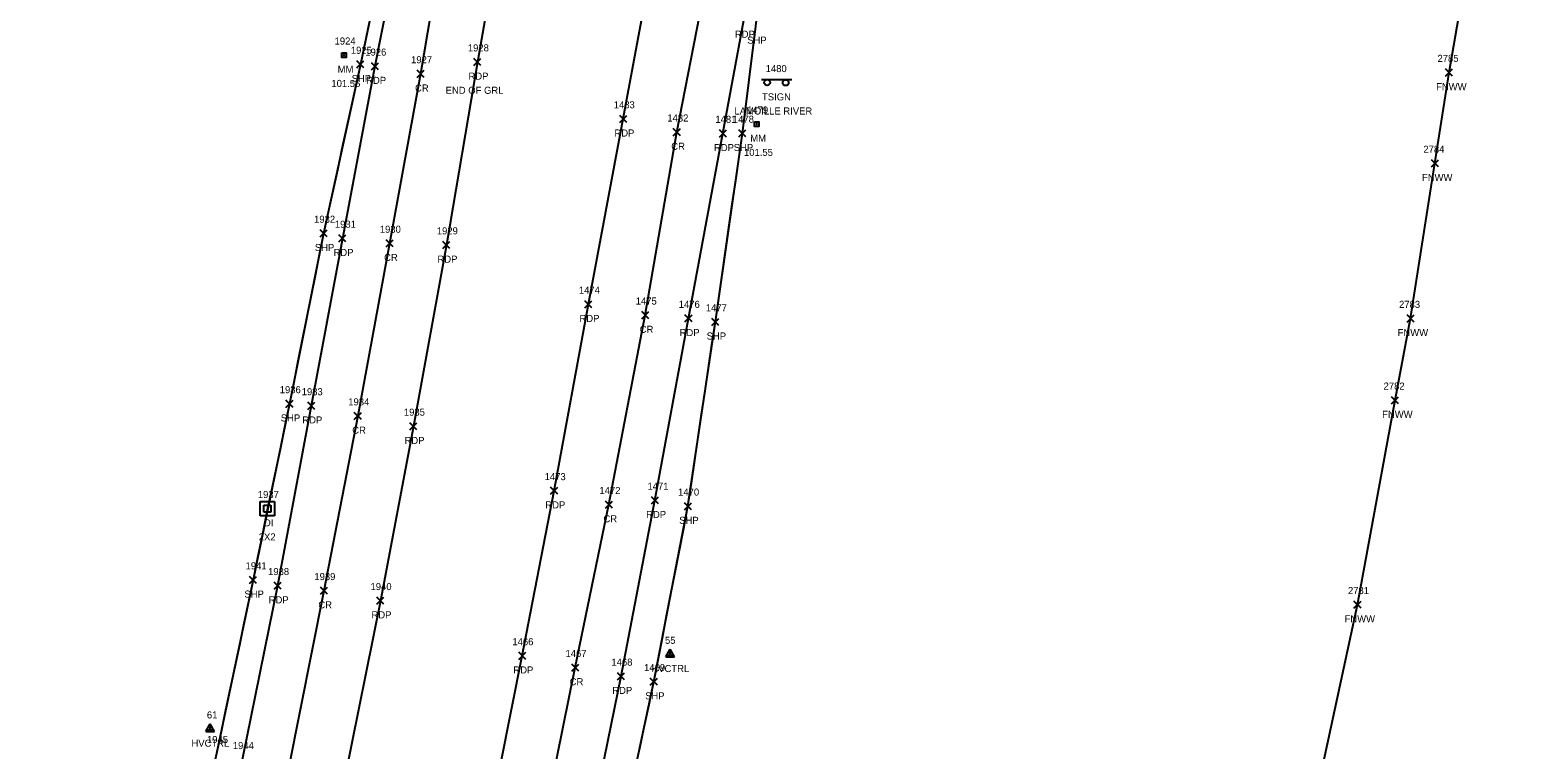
# Model space of a CAD drawing. Extents: x 1472022 to 1479249, y 777216 to 786527.
# Drawn here: x 1473450.2 to 1473876.7, y 779074.7 to 779278.4 of the extents above; entities that cross this region are included whole.
import ezdxf

# ---------------------------------------------------------------- set-up
doc = ezdxf.new("R2010")
doc.units = 0
for name, color, linetype in [('C_A', 7, 'Continuous'), ('C_I', 7, 'Continuous'), ('CPSM', 7, 'Continuous'), ('D_A', 7, 'Continuous'), ('D_C', 7, 'Continuous'), ('D_I', 7, 'Continuous'), ('DS', 7, 'Continuous'), ('L_A', 7, 'Continuous'), ('L_I', 7, 'Continuous'), ('L_TIC', 7, 'Continuous'), ('LFNC', 7, 'Continuous'), ('LSOGP', 7, 'Continuous'), ('P_A', 7, 'Continuous'), ('P_C', 7, 'Continuous'), ('P_I', 7, 'Continuous'), ('P_TIC', 7, 'Continuous'), ('PET', 7, 'Continuous'), ('PRC', 7, 'Continuous'), ('PSP', 7, 'Continuous'), ('S_A', 7, 'Continuous'), ('S_C', 7, 'Continuous'), ('S_I', 7, 'Continuous'), ('SRM', 7, 'Continuous'), ('SSGN', 7, 'Continuous')]:
    doc.layers.add(name, color=color, linetype=linetype)

msp = doc.modelspace()

# ---------------------------------------------------------------- linework, layer by layer
at = {"layer": 'CPSM'}
for p, q in [((1473630.02, 779100.99), (1473631.27, 779103.15)), ((1473630.02, 779100.99), (1473631.27, 779101.71)), ((1473630.02, 779100.99), (1473632.52, 779100.99)), ((1473632.52, 779100.99), (1473631.27, 779103.15)), ((1473631.27, 779101.71), (1473631.27, 779103.15)), ((1473631.27, 779101.71), (1473631.27, 779101.71)), ((1473631.27, 779101.71), (1473632.52, 779100.99)), ((1473499.93, 779079.86), (1473501.18, 779082.03)), ((1473499.93, 779079.86), (1473501.18, 779080.58)), ((1473499.93, 779079.86), (1473502.43, 779079.86)), ((1473502.43, 779079.86), (1473501.18, 779082.03)), ((1473501.18, 779080.58), (1473501.18, 779082.03)), ((1473501.18, 779080.58), (1473501.18, 779080.58)), ((1473501.18, 779080.58), (1473502.43, 779079.86))]:
    msp.add_line(p, q, dxfattribs=at)
at = {"layer": 'DS'}
for p, q in [((1473515.32, 779144.97), (1473519.32, 779144.97)), ((1473515.32, 779140.97), (1473515.32, 779144.97)), ((1473516.32, 779141.97), (1473516.32, 779143.97)), ((1473516.32, 779143.97), (1473518.32, 779143.97)), ((1473517.33, 779142.97), (1473517.33, 779142.97)), ((1473517.33, 779142.97), (1473517.33, 779142.97)), ((1473518.32, 779143.97), (1473518.32, 779141.97)), ((1473519.32, 779144.97), (1473519.32, 779140.97)), ((1473519.32, 779140.97), (1473515.32, 779140.97)), ((1473518.32, 779141.97), (1473516.32, 779141.97))]:
    msp.add_line(p, q, dxfattribs=at)
at = {"layer": 'L_TIC'}
for points in [[(1473850.55, 779265.41), (1473852.55, 779267.41)], [(1473852.55, 779265.41), (1473850.55, 779267.41)], [(1473846.56, 779239.7), (1473848.56, 779241.7)], [(1473848.56, 779239.7), (1473846.56, 779241.7)], [(1473839.68, 779195.79), (1473841.68, 779197.79)], [(1473841.68, 779195.79), (1473839.68, 779197.79)], [(1473835.3, 779172.66), (1473837.3, 779174.66)], [(1473837.3, 779172.66), (1473835.3, 779174.66)], [(1473824.67, 779114.79), (1473826.67, 779116.79)], [(1473826.67, 779114.79), (1473824.67, 779116.79)]]:
    msp.add_lwpolyline(points, dxfattribs=at)
at = {"layer": 'LFNC'}
msp.add_lwpolyline([(1473815.37, 779068.14), (1473825.67, 779115.79), (1473836.3, 779173.66), (1473840.68, 779196.79), (1473847.56, 779240.7), (1473851.55, 779266.41), (1473860.03, 779315.65), (1473865.47, 779349.75), (1473876.67, 779405.17)], dxfattribs=at)
at = {"layer": 'LSOGP'}
for points in [[(1473546.65, 779283.15), (1473545.15, 779275.93), (1473543.65, 779268.7), (1473542.35, 779262.72), (1473541.05, 779256.74), (1473539.74, 779250.77), (1473538.44, 779244.79), (1473537.14, 779238.81), (1473535.84, 779232.83), (1473534.54, 779226.85), (1473533.24, 779220.88), (1473532.03, 779214.85), (1473530.83, 779208.82), (1473529.62, 779202.79), (1473528.41, 779196.76), (1473527.21, 779190.73), (1473526, 779184.7), (1473524.8, 779178.67), (1473523.59, 779172.64), (1473522.3, 779166.41), (1473521.02, 779160.18), (1473519.73, 779153.95), (1473518.45, 779147.71), (1473517.33, 779142.97), (1473515.87, 779135.25), (1473514.59, 779129.02), (1473513.3, 779122.79), (1473512.01, 779116.64), (1473510.71, 779110.49), (1473509.42, 779104.35), (1473508.13, 779098.2), (1473506.83, 779092.05), (1473505.54, 779085.91), (1473504.24, 779079.76), (1473502.95, 779073.62)], [(1473622.56, 779074.68), (1473623.92, 779081.11), (1473625.28, 779087.55), (1473626.64, 779093.98), (1473627.85, 779100.19), (1473629.05, 779106.4), (1473630.26, 779112.61), (1473631.47, 779118.82), (1473632.67, 779125.03), (1473633.88, 779131.24), (1473635.09, 779137.45), (1473636.29, 779143.66), (1473637.26, 779150.18), (1473638.23, 779156.7), (1473639.2, 779163.22), (1473640.17, 779169.75), (1473641.15, 779176.27), (1473642.12, 779182.79), (1473643.09, 779189.31), (1473644.06, 779195.83), (1473645.01, 779202.5), (1473645.97, 779209.17), (1473646.92, 779215.84), (1473647.88, 779222.51), (1473648.84, 779229.18), (1473649.79, 779235.85), (1473650.75, 779242.51), (1473651.7, 779249.18), (1473652.66, 779256.78), (1473653.61, 779264.37), (1473654.56, 779271.97), (1473655.52, 779279.56)]]:
    msp.add_lwpolyline(points, dxfattribs=at)
at = {"layer": 'P_TIC'}
for points in [[(1473575.73, 779268.38), (1473577.73, 779270.38)], [(1473577.73, 779268.38), (1473575.73, 779270.38)], [(1473542.65, 779267.7), (1473544.65, 779269.7)], [(1473544.65, 779267.7), (1473542.65, 779269.7)], [(1473546.78, 779267.19), (1473548.78, 779269.19)], [(1473548.78, 779267.19), (1473546.78, 779269.19)], [(1473559.67, 779265.03), (1473561.67, 779267.03)], [(1473561.67, 779265.03), (1473559.67, 779267.03)], [(1473617, 779252.28), (1473619, 779254.28)], [(1473619, 779252.28), (1473617, 779254.28)], [(1473632.15, 779248.53), (1473634.15, 779250.53)], [(1473634.15, 779248.53), (1473632.15, 779250.53)], [(1473645.17, 779248.15), (1473647.17, 779250.15)], [(1473647.17, 779248.15), (1473645.17, 779250.15)], [(1473650.7, 779248.18), (1473652.7, 779250.18)], [(1473652.7, 779248.18), (1473650.7, 779250.18)], [(1473532.24, 779219.88), (1473534.24, 779221.88)], [(1473534.24, 779219.88), (1473532.24, 779221.88)], [(1473537.56, 779218.47), (1473539.56, 779220.47)], [(1473539.56, 779218.47), (1473537.56, 779220.47)], [(1473550.92, 779217.05), (1473552.92, 779219.05)], [(1473552.92, 779217.05), (1473550.92, 779219.05)], [(1473566.96, 779216.59), (1473568.96, 779218.59)], [(1473568.96, 779216.59), (1473566.96, 779218.59)], [(1473607.13, 779199.81), (1473609.13, 779201.81)], [(1473609.13, 779199.81), (1473607.13, 779201.81)], [(1473623.22, 779196.73), (1473625.22, 779198.73)], [(1473625.22, 779196.73), (1473623.22, 779198.73)], [(1473635.44, 779195.8), (1473637.44, 779197.8)], [(1473637.44, 779195.8), (1473635.44, 779197.8)], [(1473643.06, 779194.83), (1473645.06, 779196.83)], [(1473645.06, 779194.83), (1473643.06, 779196.83)], [(1473522.59, 779171.64), (1473524.59, 779173.64)], [(1473524.59, 779171.64), (1473522.59, 779173.64)], [(1473528.75, 779171.07), (1473530.75, 779173.07)], [(1473530.75, 779171.07), (1473528.75, 779173.07)], [(1473541.92, 779168.19), (1473543.92, 779170.19)], [(1473543.92, 779168.19), (1473541.92, 779170.19)], [(1473557.64, 779165.28), (1473559.64, 779167.28)], [(1473559.64, 779165.28), (1473557.64, 779167.28)], [(1473597.46, 779147.03), (1473599.46, 779149.03)], [(1473599.46, 779147.03), (1473597.46, 779149.03)], [(1473612.95, 779143.11), (1473614.95, 779145.11)], [(1473614.95, 779143.11), (1473612.95, 779145.11)], [(1473625.97, 779144.31), (1473627.97, 779146.31)], [(1473627.97, 779144.31), (1473625.97, 779146.31)], [(1473635.29, 779142.66), (1473637.29, 779144.66)], [(1473637.29, 779142.66), (1473635.29, 779144.66)], [(1473512.3, 779121.79), (1473514.3, 779123.79)], [(1473514.3, 779121.79), (1473512.3, 779123.79)], [(1473519.23, 779120.16), (1473521.23, 779122.16)], [(1473521.23, 779120.16), (1473519.23, 779122.16)], [(1473532.33, 779118.74), (1473534.33, 779120.74)], [(1473534.33, 779118.74), (1473532.33, 779120.74)], [(1473548.3, 779115.91), (1473550.3, 779117.91)], [(1473550.3, 779115.91), (1473548.3, 779117.91)], [(1473588.43, 779100.31), (1473590.43, 779102.31)], [(1473590.43, 779100.31), (1473588.43, 779102.31)], [(1473603.41, 779096.99), (1473605.41, 779098.99)], [(1473605.41, 779096.99), (1473603.41, 779098.99)], [(1473616.39, 779094.53), (1473618.39, 779096.53)], [(1473618.39, 779094.53), (1473616.39, 779096.53)], [(1473625.64, 779092.98), (1473627.64, 779094.98)], [(1473627.64, 779092.98), (1473625.64, 779094.98)]]:
    msp.add_lwpolyline(points, dxfattribs=at)
at = {"layer": 'PET'}
for points in [[(1473559.55, 779345.54), (1473562.13, 779344.85), (1473559.08, 779325.48), (1473547.78, 779268.19), (1473538.56, 779219.47), (1473529.75, 779172.07), (1473520.23, 779121.16), (1473510.25, 779071.91), (1473501.42, 779032.79), (1473487.97, 778980.7), (1473476.59, 778937.83), (1473460.83, 778885.95), (1473443.7, 778834.83), (1473427.04, 778789.1), (1473404.79, 778732.7), (1473383.99, 778685.53), (1473360.34, 778636.02), (1473337.25, 778590.82), (1473309.69, 778539.48), (1473284.14, 778496.13), (1473255.52, 778449.63), (1473221.14, 778399.57)], [(1473562.13, 779344.85), (1473573.79, 779342.6), (1473588.74, 779339.91), (1473585.78, 779323.26), (1473585.84, 779321.4), (1473576.73, 779269.38), (1473567.96, 779217.59), (1473558.64, 779166.28), (1473549.3, 779116.91), (1473539.05, 779065.97), (1473530.44, 779026.51), (1473516.8, 778971.79), (1473504.7, 778929.77), (1473489.22, 778877.79), (1473471.58, 778825.33), (1473455.05, 778780.13), (1473432.04, 778722.28), (1473410.95, 778674.71), (1473387.24, 778624.16), (1473365.27, 778580.65), (1473335.21, 778525.25), (1473309.35, 778481.56), (1473280.39, 778434.36), (1473245.89, 778383.45)], [(1473301.45, 778389.87), (1473329.64, 778433.49), (1473354.46, 778474.65), (1473376.14, 778512.49), (1473401.99, 778560.39), (1473423.89, 778603.83), (1473444.72, 778647.26), (1473465.48, 778692.86), (1473485.43, 778741.59), (1473500.45, 778779.97), (1473517.46, 778826.05), (1473530.33, 778868.32), (1473543.81, 778911.93), (1473556.66, 778958.65), (1473567.98, 779002.48), (1473580.14, 779054.81), (1473589.43, 779101.31), (1473598.46, 779148.03), (1473608.13, 779200.81), (1473618, 779253.28), (1473624.21, 779286.68), (1473629.11, 779313.19), (1473632.64, 779331.64)], [(1473351.95, 778416.72), (1473378.27, 778459.7), (1473399.26, 778496.93), (1473426.04, 778546.24), (1473448.78, 778590.55), (1473469.94, 778634.62), (1473491.01, 778680.96), (1473511.23, 778730.25), (1473526.94, 778770.17), (1473542.8, 778815.57), (1473557.74, 778859.7), (1473571.44, 778904.64), (1473584.34, 778950.97), (1473595.35, 778994.87), (1473607.13, 779045.13), (1473617.39, 779095.53), (1473626.97, 779145.31), (1473636.44, 779196.8), (1473646.17, 779249.15), (1473652.07, 779281.25), (1473656.8, 779307.9), (1473660.32, 779326.69), (1473648.23, 779328.95), (1473632.64, 779331.64)]]:
    msp.add_lwpolyline(points, dxfattribs=at)
at = {"layer": 'PRC'}
for points in [[(1473573.79, 779342.6), (1473570.41, 779324.08), (1473560.67, 779266.03), (1473551.92, 779218.05), (1473542.92, 779169.19), (1473533.33, 779119.74), (1473523.22, 779068.95), (1473514.33, 779029.92), (1473501.09, 778976.92), (1473489.49, 778934.86), (1473473.76, 778882.81), (1473456.11, 778830.27), (1473439.73, 778785.61), (1473416.92, 778727.46), (1473396.04, 778680.67), (1473372.49, 778630.75), (1473349.26, 778585.34), (1473321.1, 778533.63), (1473295.37, 778489.48), (1473266.55, 778442.63), (1473232.46, 778392.44)], [(1473340.44, 778424.05), (1473366.77, 778467.15), (1473388.27, 778504.09), (1473415.13, 778552.7), (1473437.21, 778597.16), (1473457.95, 778640.21), (1473479.17, 778687.02), (1473500.17, 778736.74), (1473516.94, 778774.63), (1473530.88, 778819.91), (1473544.58, 778863.11), (1473558.69, 778908.68), (1473571.41, 778953.91), (1473582.65, 778997.42), (1473594.11, 779047.2), (1473604.41, 779097.99), (1473613.95, 779144.11), (1473624.22, 779197.73), (1473633.15, 779249.53), (1473640.4, 779286.65), (1473645.03, 779310.08), (1473648.23, 779328.95)]]:
    msp.add_lwpolyline(points, dxfattribs=at)
at = {"layer": 'PSP'}
for points in [[(1473559.55, 779345.54), (1473556.55, 779328.39), (1473555.66, 779326.52), (1473543.65, 779268.7), (1473533.24, 779220.88), (1473523.59, 779172.64), (1473513.3, 779122.79), (1473502.95, 779073.62), (1473494.24, 779034.96), (1473482.21, 778985.43), (1473469.56, 778939.68), (1473453.46, 778887.37), (1473437.09, 778838.65), (1473419.76, 778792.02), (1473397.52, 778736.13), (1473377.14, 778688.43), (1473353.45, 778638.67), (1473330.09, 778593.76), (1473303, 778543.94), (1473277.25, 778499.77), (1473248.4, 778453.47), (1473214.72, 778403.13)], [(1473360.11, 778411.57), (1473386.71, 778454.12), (1473408.21, 778491.8), (1473436.32, 778544.11), (1473456.83, 778585.94), (1473478.34, 778630.94), (1473498.91, 778676.33), (1473519.57, 778726.08), (1473535.51, 778767.36), (1473551.79, 778812.35), (1473566.71, 778857.26), (1473580.68, 778902.68), (1473593.4, 778949.04), (1473604.43, 778993.44), (1473615.75, 779042.5), (1473626.64, 779093.98), (1473636.29, 779143.66), (1473644.06, 779195.83), (1473651.7, 779249.18), (1473655.52, 779279.56), (1473658.83, 779307.84), (1473662.07, 779326.37), (1473660.32, 779326.69)]]:
    msp.add_lwpolyline(points, dxfattribs=at)
at = {"layer": 'SRM'}
for points in [[(1473538.41, 779271.95), (1473539.66, 779271.95), (1473539.66, 779270.7), (1473538.41, 779270.7)], [(1473655.11, 779252.42), (1473656.36, 779252.42), (1473656.36, 779251.17), (1473655.11, 779251.17)]]:
    msp.add_lwpolyline(points, close=True, dxfattribs=at)
for centre in [(1473539.04, 779271.32), (1473655.73, 779251.8)]:
    msp.add_circle(centre, 0.0833, dxfattribs=at)
at = {"layer": 'SSGN'}
for p, q in [((1473657.05, 779264.44), (1473665.64, 779264.44)), ((1473661.07, 779263.54), (1473661.07, 779263.54))]:
    msp.add_line(p, q, dxfattribs=at)
for centre in [(1473658.71, 779263.61), (1473663.92, 779263.54)]:
    msp.add_circle(centre, 0.833, dxfattribs=at)

# ---------------------------------------------------------------- texts
at = {"layer": 'C_A'}
for p in [(1473625.96, 779096.71), (1473495.87, 779075.58)]:
    msp.add_text('HVCTRL', height=2, dxfattribs=at).set_placement(p)
at = {"layer": 'C_I'}
for s, p in [('55', (1473629.8, 779104.71)), ('61', (1473500.23, 779083.58))]:
    msp.add_text(s, height=2, dxfattribs=at).set_placement(p)
at = {"layer": 'D_A'}
msp.add_text('DI', height=2, dxfattribs=at).set_placement((1473516.38, 779137.97))
at = {"layer": 'D_C'}
msp.add_text('2X2', height=2, dxfattribs=at).set_placement((1473514.9, 779133.97))
at = {"layer": 'D_I'}
msp.add_text('1937', height=2, dxfattribs=at).set_placement((1473514.64, 779145.97))
at = {"layer": 'L_A'}
for p in [(1473847.9, 779261.41), (1473843.9, 779235.7), (1473837.02, 779191.79), (1473832.64, 779168.66), (1473822.01, 779110.79)]:
    msp.add_text('FNWW', height=2, dxfattribs=at).set_placement(p)
at = {"layer": 'L_I'}
for s, p in [('2785', (1473848.29, 779269.41)), ('2784', (1473844.3, 779243.7)), ('2783', (1473837.42, 779199.79)), ('2782', (1473833.04, 779176.66)), ('2781', (1473822.97, 779118.79))]:
    msp.add_text(s, height=2, dxfattribs=at).set_placement(p)
at = {"layer": 'P_A'}
for s, p in [('RDP', (1473649.56, 779276.25)), ('SHP', (1473653.05, 779274.56)), ('RDP', (1473574.22, 779264.38)), ('SHP', (1473541.18, 779263.7)), ('RDP', (1473545.27, 779263.19)), ('CR', (1473559.11, 779261.03)), ('RDP', (1473615.49, 779248.28)), ('CR', (1473631.58, 779244.53)), ('RDP', (1473643.66, 779244.15)), ('SHP', (1473649.24, 779244.18)), ('SHP', (1473530.77, 779215.88)), ('RDP', (1473536.05, 779214.47)), ('CR', (1473550.35, 779213.05)), ('RDP', (1473565.45, 779212.59)), ('RDP', (1473605.62, 779195.81)), ('CR', (1473622.65, 779192.73)), ('RDP', (1473633.93, 779191.8)), ('SHP', (1473641.59, 779190.83)), ('SHP', (1473521.13, 779167.64)), ('RDP', (1473527.23, 779167.07)), ('CR', (1473541.35, 779164.19)), ('RDP', (1473556.13, 779161.28)), ('RDP', (1473595.95, 779143.03)), ('CR', (1473612.39, 779139.11)), ('RDP', (1473624.46, 779140.31)), ('SHP', (1473633.83, 779138.66)), ('SHP', (1473510.84, 779117.79)), ('RDP', (1473517.72, 779116.16)), ('CR', (1473531.76, 779114.74)), ('RDP', (1473546.79, 779111.91)), ('RDP', (1473586.92, 779096.31)), ('CR', (1473602.84, 779092.99)), ('RDP', (1473614.88, 779090.53)), ('SHP', (1473624.18, 779088.98))]:
    msp.add_text(s, height=2, dxfattribs=at).set_placement(p)
at = {"layer": 'P_C'}
msp.add_text('END OF GRL', height=2, dxfattribs=at).set_placement((1473567.77, 779260.38))
at = {"layer": 'P_I'}
for s, p in [('1925', (1473540.95, 779271.7)), ('1926', (1473545.03, 779271.19)), ('1927', (1473557.98, 779269.03)), ('1928', (1473574.04, 779272.38)), ('1483', (1473615.31, 779256.28)), ('1482', (1473630.46, 779252.53)), ('1481', (1473644.05, 779252.15)), ('1478', (1473649.01, 779252.18)), ('1932', (1473530.55, 779223.88)), ('1931', (1473536.43, 779222.47)), ('1930', (1473549.14, 779221.05)), ('1929', (1473565.26, 779220.59)), ('1474', (1473605.44, 779203.81)), ('1475', (1473621.53, 779200.73)), ('1476', (1473633.69, 779199.8)), ('1477', (1473641.36, 779198.83)), ('1936', (1473520.84, 779175.64)), ('1933', (1473527.05, 779175.07)), ('1934', (1473540.22, 779172.19)), ('1935', (1473555.95, 779169.28)), ('1473', (1473595.77, 779151.03)), ('1472', (1473611.26, 779147.11)), ('1471', (1473624.84, 779148.31)), ('1470', (1473633.51, 779146.66)), ('1941', (1473511.18, 779125.79)), ('1938', (1473517.54, 779124.16)), ('1939', (1473530.63, 779122.74)), ('1940', (1473546.52, 779119.91)), ('1466', (1473586.64, 779104.31)), ('1467', (1473601.67, 779100.99)), ('1468', (1473614.65, 779098.53)), ('1469', (1473623.89, 779096.98)), ('1945', (1473500.26, 779076.62)), ('1944', (1473507.56, 779074.91))]:
    msp.add_text(s, height=2, dxfattribs=at).set_placement(p)
at = {"layer": 'S_A'}
for s, p in [('MM', (1473537.23, 779266.32)), ('TSIGN', (1473657.24, 779258.52)), ('MM', (1473653.92, 779246.8))]:
    msp.add_text(s, height=2, dxfattribs=at).set_placement(p)
at = {"layer": 'S_C'}
for s, p in [('101.55', (1473535.45, 779262.32)), ('LAMOILLE RIVER', (1473649.45, 779254.52)), ('101.55', (1473652.14, 779242.8))]:
    msp.add_text(s, height=2, dxfattribs=at).set_placement(p)
at = {"layer": 'S_I'}
for s, p in [('1924', (1473536.35, 779274.32)), ('1480', (1473658.28, 779266.52)), ('1479', (1473653.03, 779254.8))]:
    msp.add_text(s, height=2, dxfattribs=at).set_placement(p)

doc.saveas('drawing.dxf')
